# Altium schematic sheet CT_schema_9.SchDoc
size 278 x 170 mm
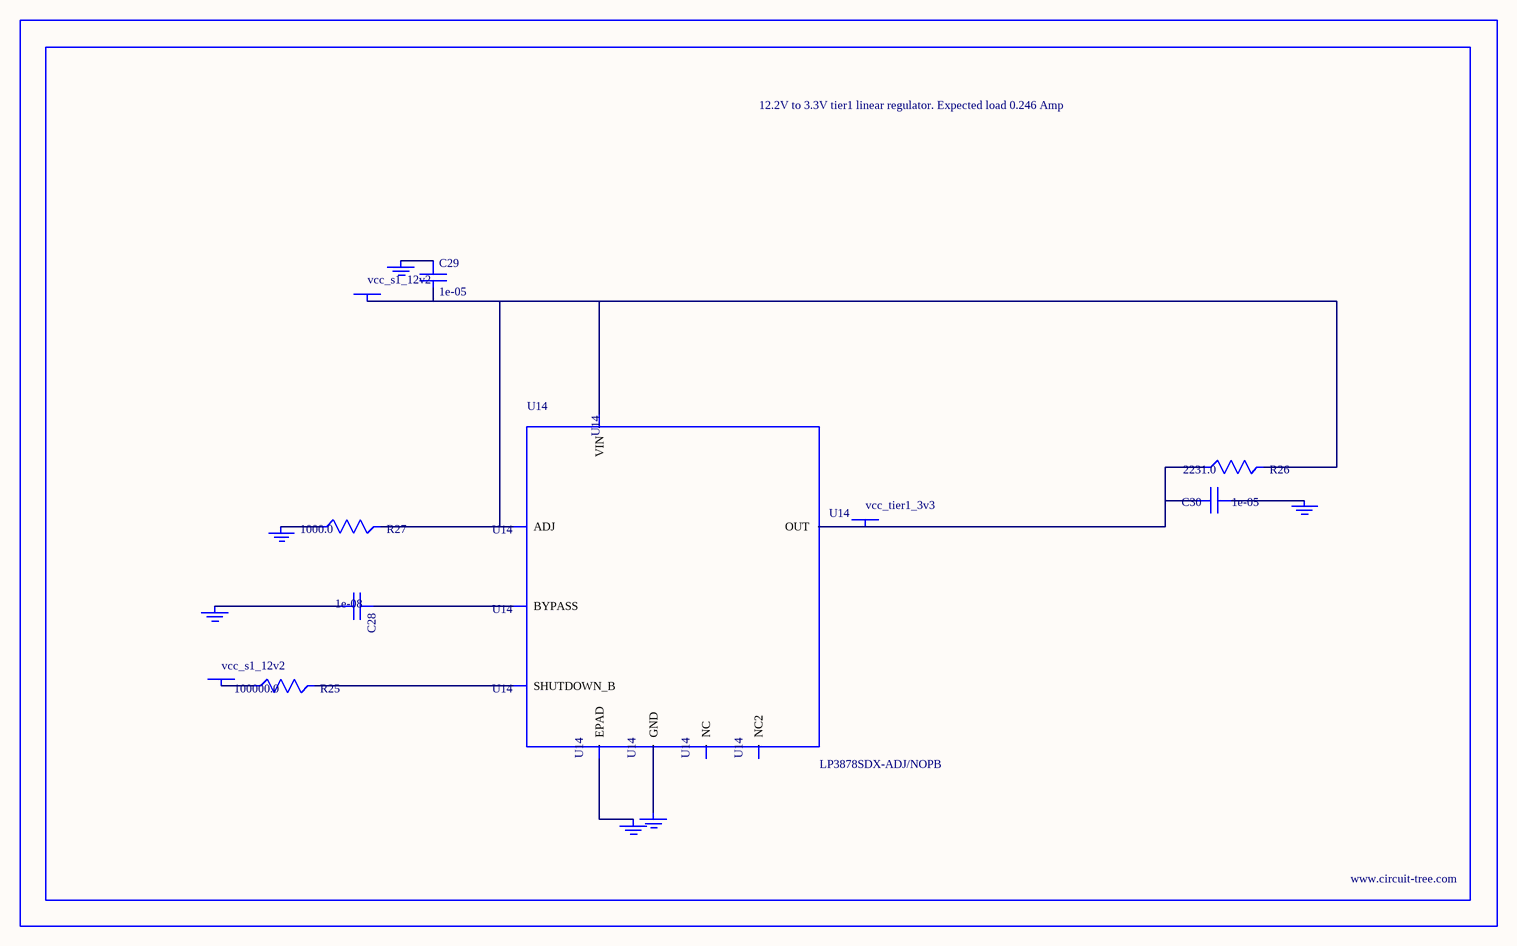
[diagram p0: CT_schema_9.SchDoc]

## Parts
BORDER8  (no value)
C28  1e-08  [C0402]
C29  1e-05  [C1210]
C30  1e-05  [C1210]
GND_INSTANCE_8_0  (no value)
GND_INSTANCE_8_1  (no value)
GND_INSTANCE_8_2  (no value)
GND_INSTANCE_8_3  (no value)
GND_INSTANCE_8_4  (no value)
GND_INSTANCE_8_5  (no value)
POWER_INSTANCE_8_0  vcc_s1_12v2
POWER_INSTANCE_8_1  vcc_s1_12v2
POWER_INSTANCE_8_2  vcc_tier1_3v3
R25  100000.0  [R0603]
R26  2231.0  [R0603]
R27  1000.0  [R0603]
U14  LP3878SDX-ADJ/NOPB  [WSON-8]

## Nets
NetC28_1: C28.1 U14.1(BYPASS)
NetC28_2: C28.2 GND_INSTANCE_8_0.0(GND)
NetC29_1: C29.1 GND_INSTANCE_8_1.0(GND)
NetC29_2: C29.2 POWER_INSTANCE_8_0.0(PWR) R26.2 R27.2 U14.4(VIN) U14.6(ADJ)
NetC30_1: C30.1 GND_INSTANCE_8_2.0(GND)
NetC30_2: C30.2 POWER_INSTANCE_8_2.0(PWR) R26.1 U14.5(OUT)
NetGND_INSTANCE_8_3_0: GND_INSTANCE_8_3.0(GND) R27.1
NetGND_INSTANCE_8_4_0: GND_INSTANCE_8_4.0(GND) U14.PAD(EPAD)
NetGND_INSTANCE_8_5_0: GND_INSTANCE_8_5.0(GND) U14.3(GND)
NetPOWER_INSTANCE_8_1_0: POWER_INSTANCE_8_1.0(PWR) R25.1
NetR25_2: R25.2 U14.8(SHUTDOWN_B)

Not connected (* = marked no-connect by the designer): U14 2(NC) 7(NC2)

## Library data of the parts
BORDER8 = BORDER_PAGE8
C28 = C0402C103K3RAC
C29 = C1210C106K5PACTU
C30 = GRM32DR61E106MA12L
GND_INSTANCE_8_0-GND_INSTANCE_8_5 = GND
POWER_INSTANCE_8_0-POWER_INSTANCE_8_2 = PWR
R25 = RC0603JR-07100KL
R26 = R26
R27 = RC0603JR-071KL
